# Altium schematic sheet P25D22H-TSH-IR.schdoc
size 127 x 101 mm
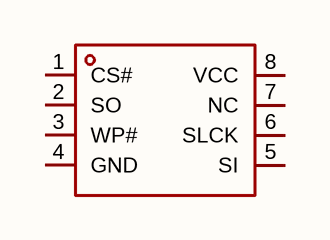
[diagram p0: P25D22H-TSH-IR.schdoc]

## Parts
U?  p25d22h-tsh-ir  [TSSOP-8_L4.4-W3.0-P0.65-LS6.4-BL]  (value not drawn)

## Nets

Not connected (* = marked no-connect by the designer): U? 1(CS#) 2(SO) 3(WP#) 4(GND) 5(SI) 6(SLCK) 7(NC) 8(VCC)

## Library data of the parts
U? = p25d22h-tsh-ir: 接口类型:SPI;存储容量:2Mbit;时钟频率(fc):85MHz;; Manufacturer: PUYA(普冉); AddInBom: yes; ModelId: 85577802f9634e7e85ffa2fd25a37b6f; ModelName: TSSOP-8_L4.4-W3.0-P0.65-LS6.4-BL-2; ModelTransform: 118.11,251.968,0,0,0,0,0,0,0; Interface: SPI; Memory Size: 2Mbit; Clock Frequency: 85MHz; Voltage - Supply: 2.3V~3.6V; Standby Supply Current: 12uA; Program / Erase Cycles: 100000次; Write Cycle Time (tWC): 8ms; Page Programming Time (Tpp): 2ms; Block Erase Time(tBE): 12ms; Data Retention - TDR (Year): 10年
